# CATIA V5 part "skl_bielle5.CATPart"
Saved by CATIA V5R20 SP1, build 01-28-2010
Part number: skl_bielle5
Publications: "Plan_ref", "PointB", "Plan_pivot_B", "Point_entraxe", "axe_ref", "Plan_pivot_entraxe", "axe_pivot_entraxe", "axe_pivot_B", "Plan_decalage"
Bounding box of the stored display mesh (mm): x -40 to 40, y -50 to 250, z -150 to 0
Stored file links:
  C:\Users\Fabien-port\Desktop\test\skl_bielle5.CATPart
  C:\Users\Fabien-port\Desktop\test\ass_skl_mecanisme_a_coulisseau.CATProduct
  C:\Users\Fabien-port\Desktop\test\mecanisme_a_coulisseau.CATProduct
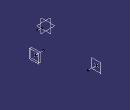
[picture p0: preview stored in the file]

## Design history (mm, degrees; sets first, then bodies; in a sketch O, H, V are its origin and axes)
External parameters (linked from other documents)
  External.largeur_bielle = 15 mm
  External.epaisseur_bielle = 8 mm
Set1
  Plane1 "Plan_ref": linked copy from another document
  Point1 "PointB": linked copy from another document
  Point2 "Point_entraxe": linked copy from another document
  Line1 "axe_ref": linked copy from another document
Set2
  Plane2 "Plan_pivot_B": type OffsetPt, RefPlane Plane1, RefPoint Point1
  Plane3 "Plan_pivot_entraxe": type OffsetPt, RefPlane Plane1, RefPoint Point2
  Line2 "axe_pivot_entraxe": type PtDir, RefPoint Point2, Direction Line1, Start 0, End 40
  Line3 "axe_pivot_B": type PtDir, RefPoint Point1, Direction Line1, Start 0, End 40
  Plane4 "Plan_decalage": type Offset, RefPlane Plane3, Offset 9 {= External.epaisseur_bielle +1mm}
Body1 (main body)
